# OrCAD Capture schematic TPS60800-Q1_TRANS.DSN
size D; title: TPS60800-Q1: Unregulated, 200mA, Automotive, Charge Pump Voltage Inverter; rev: 1.0; note: Datasheet: SLVSI54     EVM: SLVUDA8; note: Synchronous Step Down Converter
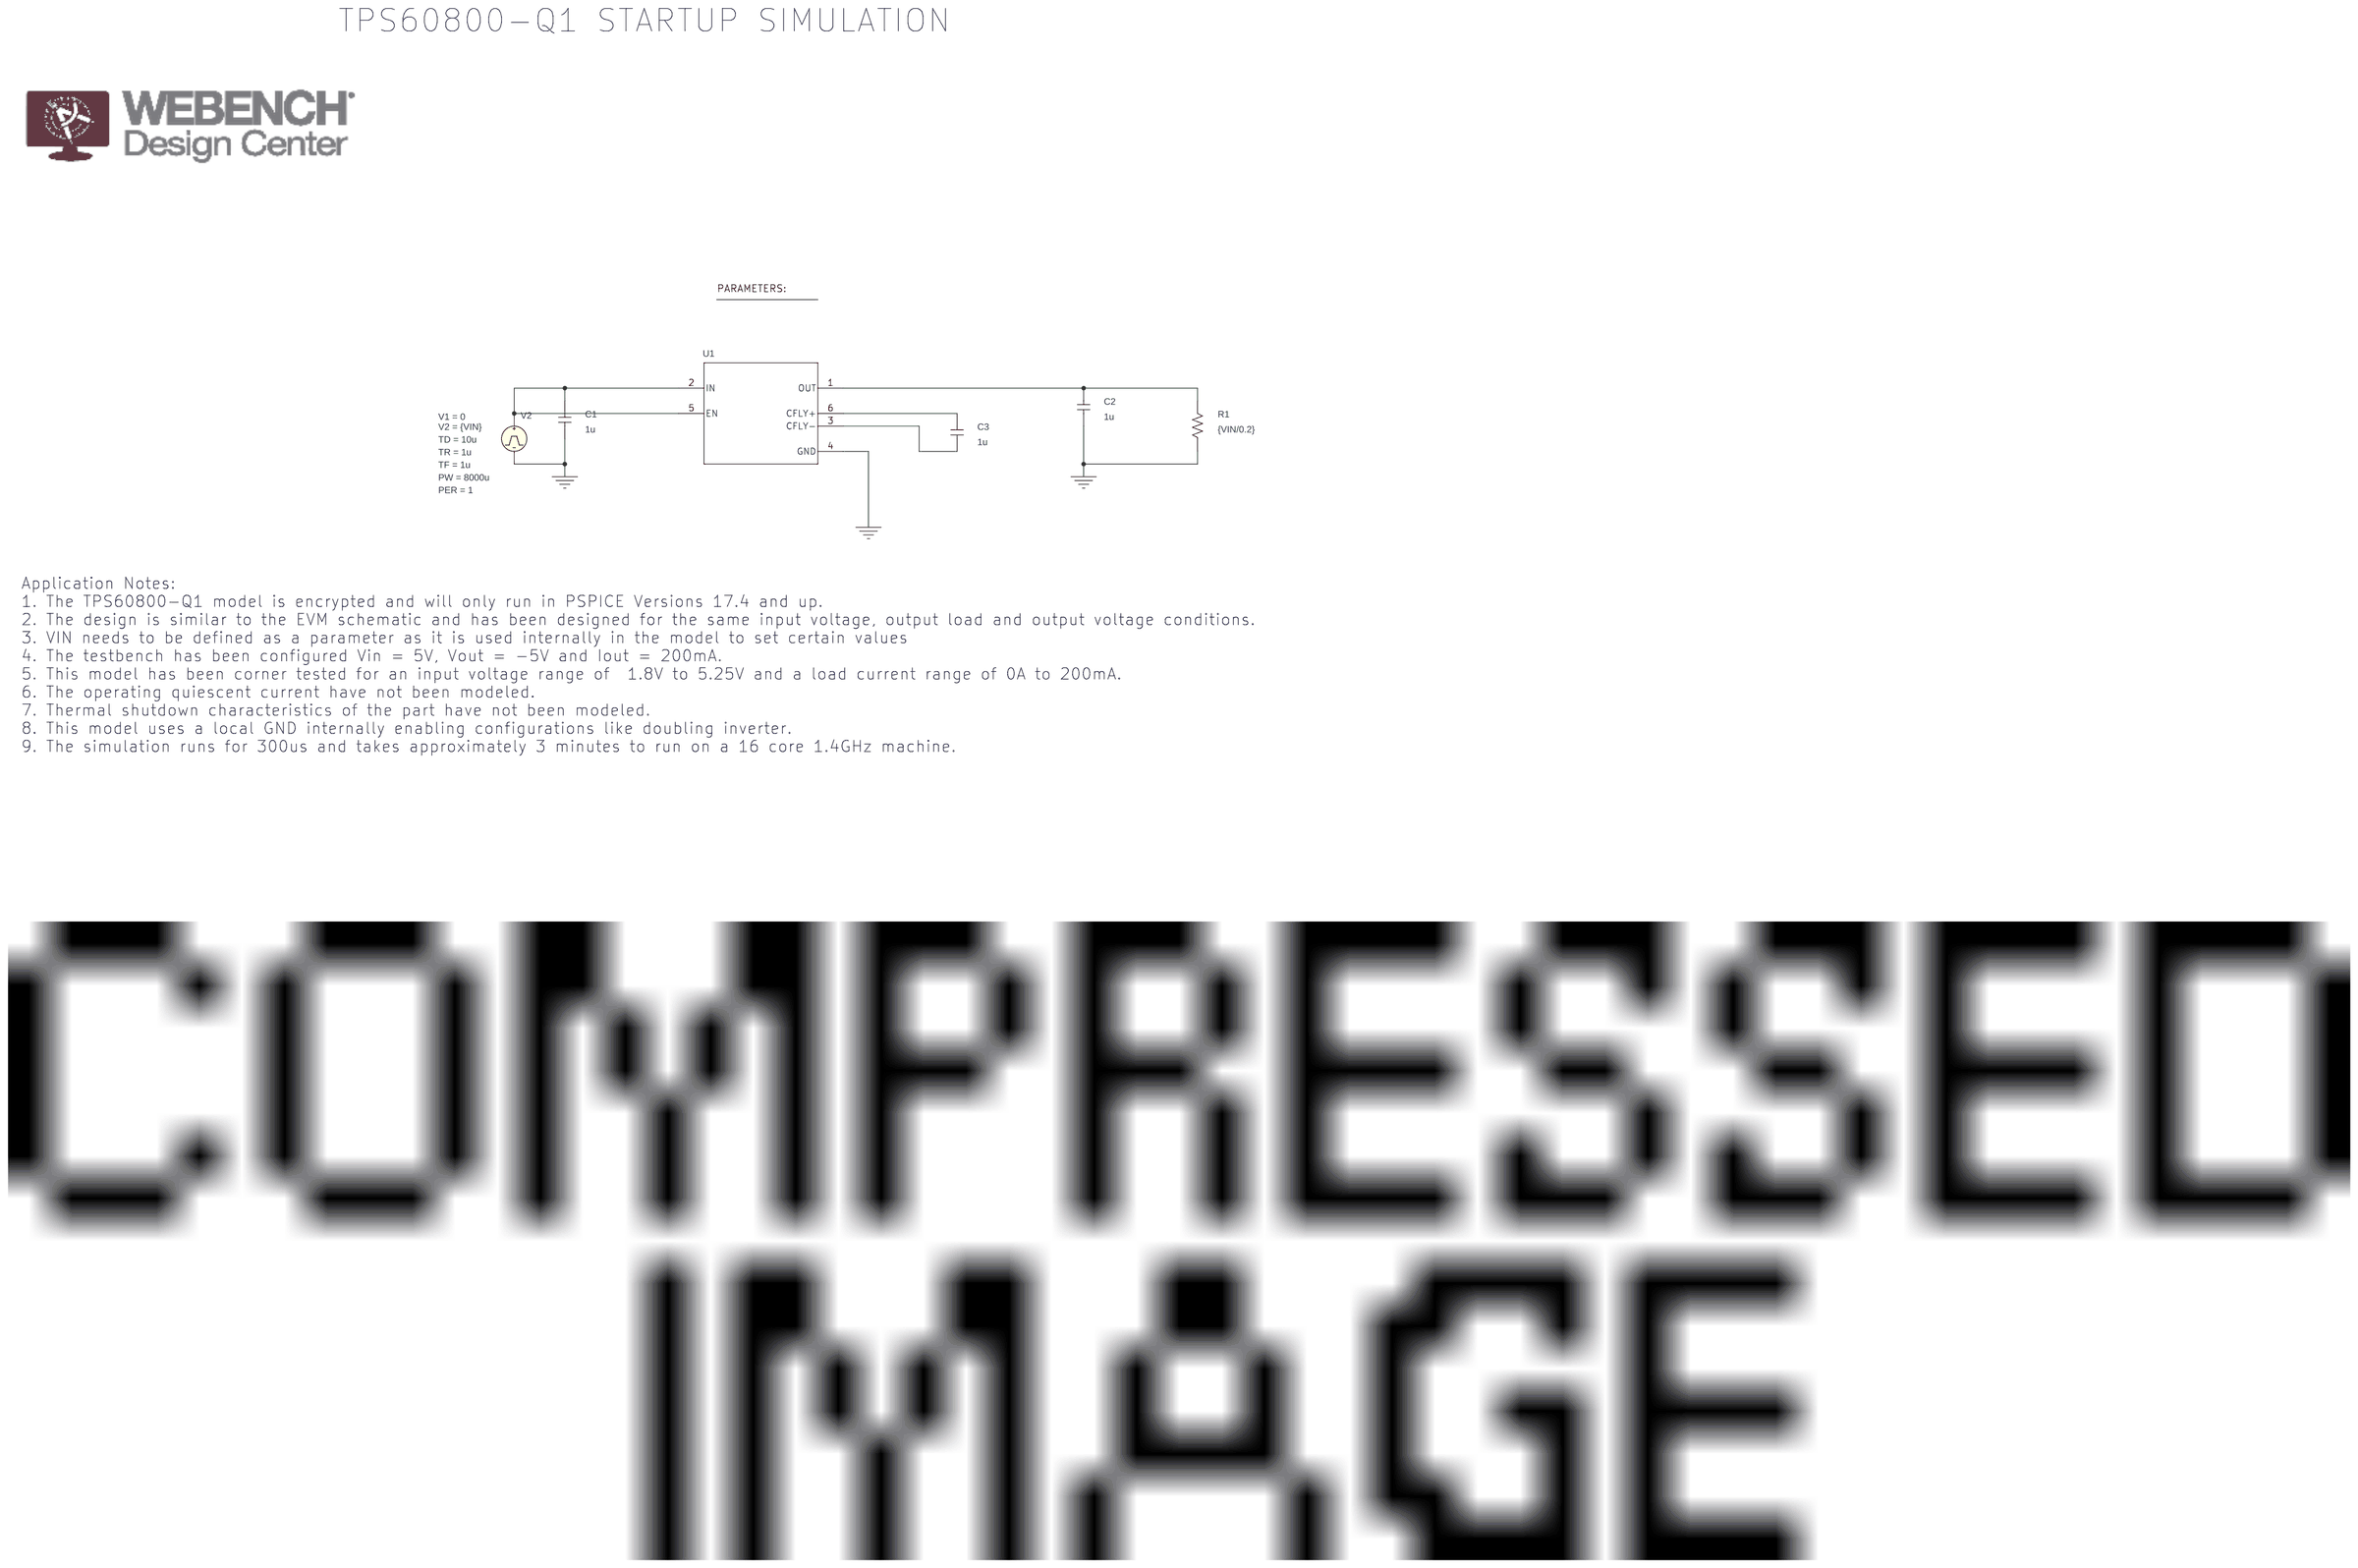
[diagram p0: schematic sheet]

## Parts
1  PARAM
C1  1u  [cap196]
C2  1u  [cap196]
C3  1u  [cap196]
R1  {VIN/0.2}  [AXRC05]
U1  Value  [DRL0006A-MFG]
V2  VPULSE

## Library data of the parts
1 = PARAM: VIN: 5
C1-C3 = C
R1 = R
U1 = TPS60800-Q1DRL_TRANS
V2 = VPULSE: PER: 1; PW: 8000u; TD: 10u; TF: 1u; TR: 1u; V1: 0; V2: {VIN}

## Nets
0: C1.1 C2.1 R1.1 U1.4(GND) V2.2(-)
N16769383: C1.2 U1.2(IN) U1.5(EN) V2.1(+)
N16769475: C2.2 R1.2 U1.1(OUT)
N16769484: C3.2 U1.6(CFLY+)
N16769488: C3.1 U1.3(CFLY-)

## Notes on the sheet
- TPS60800-Q1 STARTUP SIMULATION
- Application Notes:
  1. The TPS60800-Q1 model is encrypted and will only run in PSPICE Versions 17.4 and up.
  2. The design is similar to the EVM schematic and has been designed for the same input voltage, output load and output voltage conditions.
  3. VIN needs to be defined as a parameter as it is used internally in the model to set certain values
  4. The testbench has been configured Vin = 5V, Vout = -5V and Iout = 200mA.
  5. This model has been corner tested for an input voltage range of  1.8V to 5.25V and a load current range of 0A to 200mA.
  6. The operating quiescent current have not been modeled.
  7. Thermal shutdown characteristics of the part have not been modeled.
  8. This model uses a local GND internally enabling configurations like doubling inverter.
  9. The simulation runs for 300us and takes approximately 3 minutes to run on a 16 core 1.4GHz machine.
